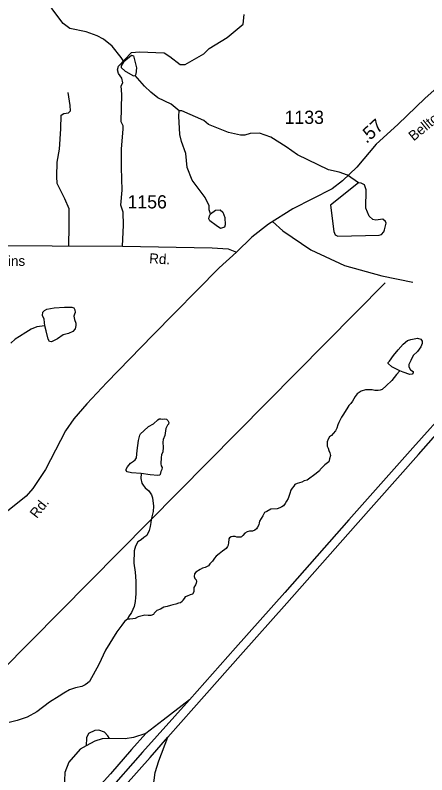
# Model space of a CAD drawing. Extents: x 2056842 to 2160602, y 826753 to 1016856.
# Drawn here: x 2105624 to 2109514, y 905515 to 912699 of the extents above; entities that cross this region are included whole.
import ezdxf

# ---------------------------------------------------------------- set-up
doc = ezdxf.new("R2010")
doc.units = 0
for name, color, linetype in [('Exist Hydrographic Creek Single Shore', 7, 'Continuous'), ('Exist Hydrographic Misc Water Feature', 7, 'Continuous'), ('Exist Road Non-System Type 51', 7, 'Continuous'), ('Exist Road Primary Interstate Divided Center Attributed', 7, 'Continuous'), ('Exist Road Primary Interstate Ramp 1 Lane Attributed', 7, 'Continuous'), ('Exist Road Secondary Mileage Hundredths English Label', 7, 'Continuous'), ('Exist Road Secondary Type 51 Attributed', 7, 'Continuous'), ('Exist Road Secondary Type 51 Label', 7, 'Continuous'), ('Exist Road Secondary Type 51 Number Label', 7, 'Continuous'), ('Exist Utilities Electrical Transmission Line', 7, 'Continuous')]:
    doc.layers.add(name, color=color, linetype=linetype)

msp = doc.modelspace()

# ---------------------------------------------------------------- linework, layer by layer
at = {"layer": 'Exist Hydrographic Creek Single Shore'}
for points in [[(2109258.6, 909336.7), (2109227, 909299.7), (2109183.9, 909242.8), (2109129.5, 909192.6), (2109091.5, 909159.3), (2109073.7, 909153.2), (2109053.6, 909149.2), (2109021.6, 909149.1), (2108997.6, 909154.9), (2108971.5, 909156.9), (2108935.7, 909156.7), (2108893.6, 909142.6), (2108855.5, 909118.5), (2108837.9, 909092.5), (2108811.8, 909050.4), (2108795.8, 909026.3), (2108776.1, 909006.3), (2108758.1, 908976.3), (2108720.4, 908916.1), (2108708.3, 908896.1), (2108682.6, 908848), (2108674.6, 908824.1), (2108662.5, 908794), (2108650.8, 908768), (2108630.7, 908743.9), (2108612.9, 908723.8), (2108594.9, 908711.8), (2108581.1, 908689.7), (2108573.1, 908665.6), (2108571.1, 908637.7), (2108573.3, 908621.7), (2108581.3, 908605.8), (2108589.3, 908583.7), (2108597.3, 908559.8), (2108603.5, 908535.9), (2108595.5, 908503.8), (2108587.5, 908475.8), (2108549.8, 908447.7), (2108507.7, 908401.5), (2108499.7, 908391.5), (2108486, 908379.5), (2108470, 908365.5), (2108382.2, 908303.2), (2108356.4, 908295.1), (2108332.4, 908283), (2108288.3, 908268.9), (2108268.2, 908260.8), (2108256.3, 908244.8), (2108242.6, 908226.7), (2108228.6, 908206.6), (2108220.6, 908176.7), (2108204.9, 908128.6), (2108188.9, 908104.6), (2108174.9, 908080.5), (2108159.1, 908058.5), (2108145, 908050.5), (2108125.1, 908040.4), (2108101.1, 908030.4), (2108041, 908026.2), (2108001, 908006), (2107981.3, 907995.9), (2107965.4, 907965.9), (2107933.6, 907913.8), (2107929.5, 907897.8), (2107927.6, 907877.8), (2107915.5, 907855.8), (2107903.6, 907841.7), (2107887.8, 907829.7), (2107865.9, 907819.6), (2107837.8, 907819.5), (2107817.7, 907813.5), (2107795.8, 907799.4), (2107775.9, 907779.3), (2107763.8, 907767.3), (2107756, 907763.3), (2107740, 907763.2), (2107720.1, 907763.1), (2107703.9, 907769.2), (2107679.7, 907769.1), (2107664.1, 907765.1), (2107648.1, 907755), (2107644, 907747)], [(2107644, 907747), (2107642, 907735), (2107640.1, 907718.9), (2107640.1, 907710.9), (2107638.3, 907686.9), (2107630.3, 907672.9), (2107618.4, 907656.9), (2107604.3, 907644.8), (2107582.3, 907630.8), (2107552.6, 907604.7), (2107524.5, 907582.6), (2107506.7, 907564.5), (2107488.6, 907536.5), (2107476.9, 907522.5), (2107464.8, 907510.4), (2107450.9, 907492.4), (2107420.7, 907476.2), (2107394.9, 907470.2), (2107370.9, 907456.1), (2107331.1, 907432.1), (2107319, 907416), (2107317, 907392), (2107323.3, 907372.1), (2107335.2, 907360), (2107339.3, 907344.1), (2107335.2, 907328), (2107329.3, 907312), (2107313.5, 907288), (2107313.5, 907266), (2107313.5, 907246.1), (2107299.6, 907223.9), (2107277.6, 907217.9), (2107249.7, 907205.8), (2107229.8, 907197.8), (2107221.8, 907183.7), (2107209.7, 907167.7), (2107203.8, 907153.7), (2107187.8, 907141.6), (2107167.9, 907137.6), (2107142.1, 907129.5), (2107114, 907121.4), (2107092, 907115.4), (2107060, 907107.3), (2107030.1, 907099.2), (2106998.1, 907083.1), (2106964.1, 907068.9), (2106938.2, 907042.9), (2106930.3, 907030.9), (2106906.3, 907022.8), (2106882.3, 907022.7), (2106850.3, 907024.6), (2106810.3, 907016.4), (2106786.3, 907008.4), (2106758.4, 906992.3), (2106736.5, 906990.3), (2106708.6, 906988.1), (2106684.6, 906988.1)], [(2106684.6, 906988.1), (2106658.6, 906964), (2106630.7, 906930), (2106584.7, 906867.9), (2106479.3, 906693.5), (2106415.8, 906557.3), (2106326.4, 906397.1), (2106308.3, 906381), (2106284.3, 906365), (2106252.6, 906350.8), (2106192.7, 906338.6), (2106138.5, 906318.5), (2106082.6, 906288.3), (2106038.9, 906258.1), (2105947, 906201.9), (2105829.3, 906111.5), (2105737.3, 906059.3), (2105643.5, 906029), (2105567.7, 906008.7)]]:
    msp.add_lwpolyline(points, dxfattribs=at)
at = {"layer": 'Exist Hydrographic Misc Water Feature'}
for points in [[(2106650.6, 912262), (2106626.4, 912299.9), (2106542.1, 912407.5), (2106457.8, 912471.3), (2106397.7, 912503.1), (2106293.8, 912542.8), (2106139.6, 912572.3), (2106077.6, 912622), (2105971, 912761.8), (2105930.8, 912839.6), (2105916.5, 912889.6), (2105914.6, 912949.6), (2105922.2, 913009.6), (2105922, 913089.5)], [(2106650.6, 912262), (2106722.3, 912320.2), (2106742.2, 912314.2), (2106770.7, 912200.3), (2106764.8, 912142.3), (2106756.8, 912128.3)], [(2106650.6, 912262), (2106624.5, 912219.9), (2106626.8, 912203.9), (2106664.9, 912170), (2106670.9, 912166)], [(2106670.9, 912166), (2106743, 912124.3), (2106756.8, 912128.3)], [(2107173.9, 911793.6), (2107097.8, 911857.4), (2106971.5, 911919), (2106905.2, 911970.8), (2106847.4, 912026.6), (2106756.8, 912128.3)], [(2107469.1, 910820.6), (2107458.9, 910858.7), (2107456.8, 910894.7), (2107420.5, 910976.5), (2107296.1, 911140.1), (2107249.5, 911257.9), (2107237, 911389.9), (2107196.8, 911505.7), (2107180.6, 911571.7), (2107170.2, 911745.6), (2107173.9, 911793.6)], [(2108867.8, 911113), (2108763.6, 911184.7), (2108685.5, 911214.4), (2108585.6, 911236.2), (2108293, 911379.2), (2108184.8, 911454.9), (2108040.6, 911546.4), (2107932.5, 911582), (2107844.6, 911581.8), (2107794.5, 911563.7), (2107754.6, 911565.5), (2107640.6, 911591.1), (2107450.3, 911666.5), (2107406, 911702.4), (2107197.8, 911793.7), (2107173.9, 911793.6)], [(2108867.8, 911113), (2108602.7, 910902.3), (2108635.3, 910652.4)], [(2109113.2, 910669.8), (2109129, 910731.9), (2109125.1, 910748), (2109098.9, 910769.9), (2109032.9, 910759.6), (2109002.7, 910767.5), (2108970.7, 910797.4), (2108952.9, 910835.3), (2108938.5, 910875.3), (2108940, 911047.3), (2108925.8, 911095.2), (2108893.8, 911111.2), (2108867.8, 911113)], [(2107523.3, 910708.9), (2107465, 910754.7), (2107453.1, 910772.7), (2107459.1, 910802.6), (2107469.1, 910820.6)], [(2107469.1, 910820.6), (2107518.8, 910856.8), (2107562.8, 910856.9), (2107586.8, 910835.1), (2107607.1, 910787.1)], [(2107607.1, 910787.1), (2107607.3, 910717.1), (2107601.4, 910693.1), (2107565.3, 910683.1), (2107523.3, 910708.9)], [(2108635.3, 910652.4), (2108649.4, 910620.4), (2108673.6, 910608.5), (2109063.4, 910617.7), (2109087.4, 910625.7), (2109109.3, 910649.8), (2109113.2, 910669.8)], [(2105905.8, 909760.4), (2105897.3, 909824.5), (2105882.3, 909858.7), (2105886.6, 909890.7), (2105901.6, 909907.8), (2105922.9, 909919.5), (2105991.2, 909931.3), (2106090.4, 909938.7), (2106159.8, 909938.7), (2106177.9, 909931.3), (2106188.6, 909913.1), (2106189.7, 909888.6), (2106183.3, 909870.4), (2106179, 909851.2), (2106183.3, 909821.3), (2106196.1, 909787.1), (2106198.2, 909765.8), (2106190.7, 909732.7), (2106168.3, 909708.1), (2106128.8, 909688.9), (2106077.6, 909675), (2106024.3, 909638.7), (2105966.6, 909608.8), (2105948.5, 909614.2), (2105934.6, 909634.5), (2105916.5, 909714.5), (2105905.8, 909760.4)], [(2105905.8, 909760.4), (2105829, 909750.8), (2105776.7, 909728.4), (2105726.4, 909698.8), (2105666.3, 909660.7), (2105625.2, 909635.5), (2105583.6, 909596)], [(2109258.6, 909336.7), (2109185, 909373), (2109148.7, 909405.1), (2109148.7, 909415.7), (2109160.4, 909427.5), (2109199.9, 909480.9), (2109242.6, 909533.2), (2109291.7, 909588.7), (2109332.2, 909623.9), (2109363.2, 909632.5), (2109426.1, 909644.2), (2109459.2, 909634.6), (2109470.9, 909616.5), (2109470.9, 909593), (2109459.2, 909564.2), (2109425, 909517.2), (2109386.6, 909481.9), (2109363.2, 909435), (2109344, 909394.4), (2109342.9, 909372), (2109361, 909345.3), (2109384.5, 909330.3), (2109386.6, 909317.5), (2109376, 909303.6), (2109354.6, 909300.4), (2109291.7, 909322.9), (2109258.6, 909336.7)], [(2106813.9, 908365.1), (2106724.3, 908371.5), (2106681.6, 908381.1), (2106672, 908392.9), (2106674.1, 908405.7), (2106684.8, 908429.2), (2106713.6, 908461.2), (2106741.3, 908481.5), (2106758.4, 908493.2), (2106772.3, 908513.5), (2106776.5, 908582.9), (2106790.4, 908675.8), (2106801.1, 908727.1), (2106808.6, 908739.9), (2106841.6, 908769.8), (2106885.4, 908809.3), (2106931.3, 908836), (2106970.8, 908873.3), (2106985.7, 908880.8), (2107000.6, 908883), (2107016.6, 908879.8), (2107033.7, 908881.9), (2107052.9, 908878.7), (2107065.7, 908865.9), (2107075.3, 908846.7), (2107073.2, 908832.8), (2107062.5, 908821), (2107048.6, 908790.1), (2107039, 908722.8), (2107023, 908687.6), (2107018.8, 908661.9), (2107024.1, 908611.8), (2107019.8, 908569.1), (2107006, 908540.2), (2107002.8, 908514.6), (2106999.6, 908456.9), (2107003.8, 908437.5), (2107012.4, 908420.4), (2107010.2, 908402.3), (2106999.6, 908385.2), (2106995.3, 908354.2), (2106987.8, 908347.8), (2106970.8, 908345.7), (2106900.3, 908352.1), (2106813.9, 908365.1)], [(2106813.9, 908365.1), (2106810.7, 908316.9), (2106820.5, 908274.3), (2106834.5, 908254.4), (2106852.5, 908230.4), (2106886.8, 908200.6), (2106913.1, 908164.4), (2106922.7, 908133.4), (2106931.3, 908055.5), (2106929.1, 908006.4), (2106909.5, 907928.7), (2106905.6, 907900.7), (2106899.9, 907864.6), (2106889.9, 907824.6), (2106868.1, 907778.6), (2106840, 907758.5), (2106814, 907738.4), (2106782.4, 907718.3), (2106760.3, 907678.2), (2106748.6, 907634.2), (2106746.7, 907518.2), (2106759, 907430.3), (2106765.9, 907347), (2106763.7, 907226.3), (2106762.7, 907192.2), (2106757.8, 907154.3), (2106750, 907106.2), (2106722.3, 907050.2), (2106694.2, 907008.1), (2106684.6, 906988.1)]]:
    msp.add_lwpolyline(points, dxfattribs=at)
at = {"layer": 'Exist Road Non-System Type 51'}
for points in [[(2106637, 910516), (2106646.8, 910712.7), (2106643.2, 910835), (2106623.4, 910903.3), (2106634.2, 911043.5), (2106627.9, 911260.1), (2106629.7, 911436.3), (2106645.9, 911621.4), (2106645.9, 911653.8), (2106626.1, 911691.5), (2106632.4, 911949.5), (2106625.2, 912030.4), (2106641.4, 912060.9), (2106632.4, 912102.3), (2106601.8, 912149), (2106591.1, 912183.2), (2106601.8, 912217.3), (2106724, 912346.7), (2106799.4, 912353.9), (2107031.2, 912343.1), (2107086.9, 912309), (2107183.9, 912233.5), (2107229.7, 912234.4), (2107407.5, 912333.3), (2107456, 912383.6), (2107628.5, 912489.6), (2107777.5, 912615.5), (2107789.2, 912704.5)], [(2106132.5, 910516.7), (2106133.9, 910704.6), (2106133.9, 910866.4), (2106094.4, 910963.5), (2106021.6, 911108.2), (2106018, 911174.7), (2106019.8, 911309.5), (2106043.2, 911431.8), (2106055.8, 911624.1), (2106060.2, 911752.6), (2106083.6, 911768.8), (2106126.7, 911776), (2106148.3, 911794), (2106142.9, 911844.3), (2106124.9, 911968.3)], [(2108057.5, 910746.5), (2108154.8, 910659.7), (2108417, 910479.9), (2108736.8, 910332.5), (2109088.9, 910235.5), (2109383.5, 910174.4)]]:
    msp.add_lwpolyline(points, dxfattribs=at)
at = {"layer": 'Exist Road Primary Interstate Divided Center Attributed'}
for points in [[(2107068.4, 905870.1), (2107313.1, 906149), (2107754, 906645.9), (2108191.2, 907139.1), (2108841.8, 907873.6), (2109434.7, 908543.3), (2109789.2, 908944.8)], [(2109737, 909006), (2109382.5, 908608.2), (2108777, 907927.6), (2108171.4, 907239.9), (2107705.4, 906716.1), (2107270.1, 906223.2)], [(2107270.1, 906223.2), (2106829, 905727.7), (2106485.3, 905338.8), (2106202.8, 905031), (2105965.3, 904789.8), (2105828.7, 904661.1)], [(2105703.8, 904430.2), (2106055.2, 904762.8), (2106260.4, 904973.4), (2106537.5, 905272.2), (2106899.2, 905677.3), (2107068.4, 905870.1)]]:
    msp.add_lwpolyline(points, dxfattribs=at)
at = {"layer": 'Exist Road Primary Interstate Ramp 1 Lane Attributed'}
for points in [[(2107270.1, 906223.2), (2107024.2, 906032.5), (2106860.3, 905904.3)], [(2106376.9, 905935.6), (2106315.9, 905905), (2106299.5, 905866.3), (2106296.5, 905788.8)], [(2106515.5, 905857.3), (2106500.6, 905882.7), (2106469.3, 905918.4), (2106414.2, 905937.8), (2106376.9, 905935.6)], [(2106860.3, 905904.3), (2106723.3, 905755.2), (2106523.7, 905524.2), (2106344.6, 905327.1), (2106263.7, 905242.5), (2106199, 905232), (2106121.5, 905219.4), (2106091.7, 905205.2)], [(2106515.5, 905857.3), (2106445.5, 905854.3), (2106377, 905833.5), (2106296.5, 905788.8)], [(2106860.3, 905904.3), (2106741.1, 905867), (2106663.7, 905856.6), (2106515.5, 905857.3)], [(2106928.1, 905392.3), (2106946, 905536.9), (2106981.7, 905647.2), (2107068.4, 905870.1)], [(2106296.5, 905788.8), (2106239.9, 905758.9), (2106131.2, 905635.2), (2106092.4, 905538.3), (2106088.7, 905385.6), (2106091.7, 905205.2)]]:
    msp.add_lwpolyline(points, dxfattribs=at)
at = {"layer": 'Exist Road Secondary Type 51 Attributed'}
for points in [[(2110051.9, 912322.3), (2109946.8, 912256.7), (2109821.6, 912186.2), (2109663.6, 912060.4), (2109497.5, 911914), (2109238.9, 911664.2), (2109036, 911479.1), (2108851.9, 911260.8), (2108717.3, 911133.2), (2108620.3, 911057.7), (2108247.7, 910866.4), (2108019.6, 910722.6), (2107859.8, 910600.4), (2107717.1, 910459.4)], [(2104095, 910825.1), (2104193.1, 910684.9), (2104302.6, 910586.1), (2104422.9, 910532.1), (2104651, 910523.2), (2104916.7, 910523.2), (2105973.5, 910516.9), (2106637, 910516), (2107484.5, 910499.8), (2107636.3, 910489.9), (2107717.1, 910459.4)], [(2107717.1, 910459.4), (2107551, 910309.3), (2106924.9, 909672.1), (2106491.1, 909225.3), (2106300.7, 909022.2), (2106178.5, 908882), (2106101.3, 908768.7), (2105911.7, 908402.9), (2105789.6, 908221.3), (2105728.5, 908151.2), (2105310.9, 907819.5), (2105125.8, 907647), (2104960.5, 907447.4), (2104807, 907254.2), (2104713.5, 907110.3), (2104621.9, 906923.4), (2104524.9, 906713.1), (2104473.7, 906562.9), (2104410.8, 906313.1), (2104268, 905587.7), (2104230.3, 905307.3), (2104202.5, 905126.6)]]:
    msp.add_lwpolyline(points, dxfattribs=at)
at = {"layer": 'Exist Utilities Electrical Transmission Line'}
msp.add_lwpolyline([(2103917.2, 905512.7), (2103959.3, 905544.8), (2104005.1, 905575.1), (2104059.1, 905611.2), (2104090.8, 905629.3), (2104130.9, 905651.5), (2104170.8, 905675.5), (2104214.7, 905699.8), (2104278.6, 905721.8), (2104778, 905897.3), (2104820, 905913.5), (2104863.8, 905943.8), (2104919.7, 905979.8), (2105209, 906212.7), (2109122, 910166.6)], dxfattribs=at)

# ---------------------------------------------------------------- texts
at = {"layer": 'Exist Road Secondary Mileage Hundredths English Label'}
msp.add_text('.57', height=125, rotation=42.36902, dxfattribs=at).set_placement((2108944.5, 911480.3))
at = {"layer": 'Exist Road Secondary Type 51 Label'}
for s, rotation, p in [('Belltown', 39.32723, (2109389.9, 911504.6)), ('Watkins', 0.36294, (2105267, 910325.4)), ('Rd.', 356.63008, (2106888.7, 910353.3)), ('Rd.', 52.09722, (2105828.6, 907934.1))]:
    msp.add_text(s, height=95, rotation=rotation, dxfattribs=at).set_placement(p)
at = {"layer": 'Exist Road Secondary Type 51 Number Label'}
for s, p in [('1133', (2108170.4, 911671.3)), ('1156', (2106685.7, 910871.5))]:
    msp.add_text(s, height=125, dxfattribs=at).set_placement(p)

doc.saveas('drawing.dxf')
